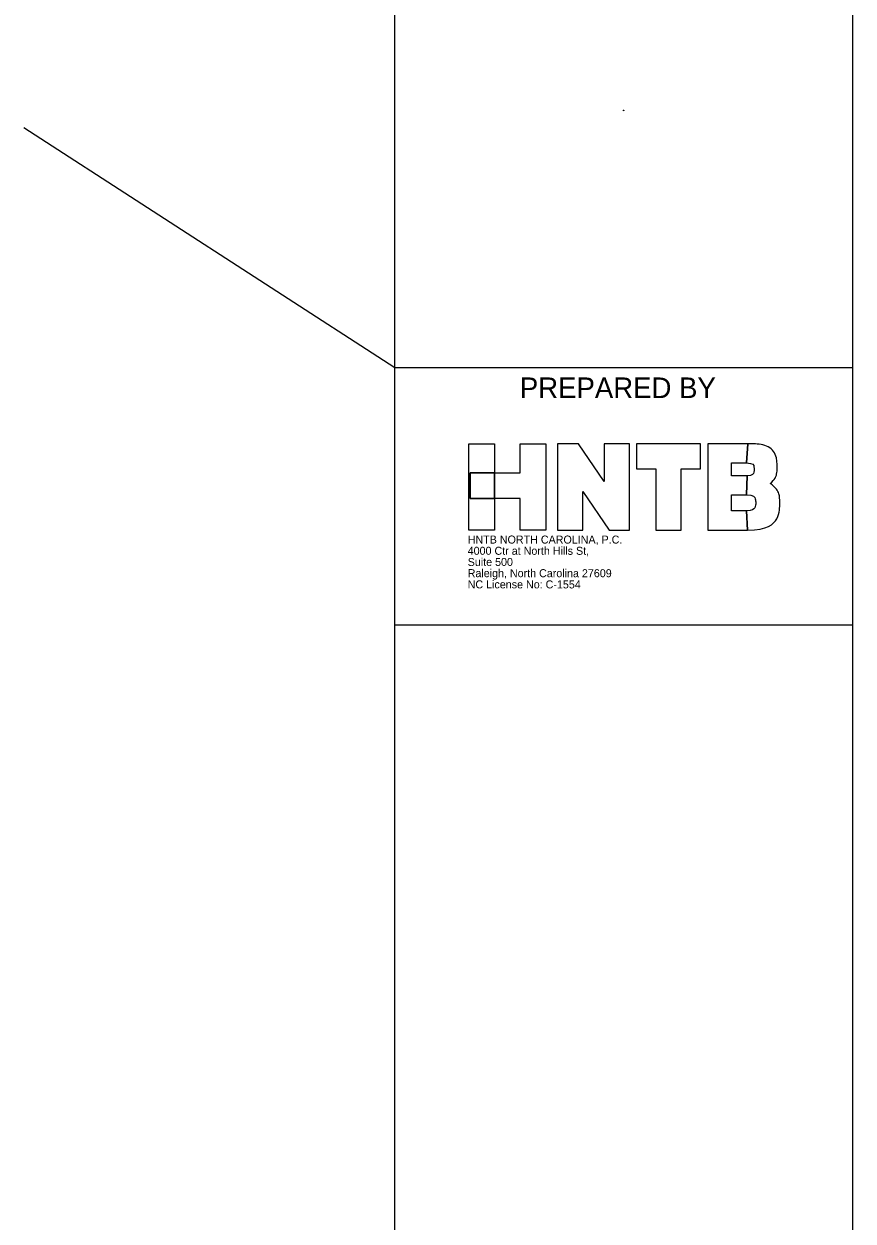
# Model space of a CAD drawing. Extents: x 2.51 to 3.27, y 0.05 to 1.8.
# Drawn here: x 2.5091 to 2.8109, y 0.9253 to 1.3613 of the extents above; entities that cross this region are included whole.
import ezdxf

# ---------------------------------------------------------------- set-up
doc = ezdxf.new("R2010")
doc.units = 0
for name, color, linetype in [('Default', 7, 'Continuous'), ('Draft_RDY_Construction_Class_Element', 7, 'Continuous'), ('Raster_Level_0', 7, 'Continuous'), ('Scratch_Level_0', 7, 'Continuous'), ('Sheet_PE_Seal_Cell', 7, 'Continuous'), ('Sheet_Plan_CELL', 7, 'Continuous')]:
    doc.layers.add(name, color=color, linetype=linetype)

msp = doc.modelspace()

# ---------------------------------------------------------------- linework, layer by layer
at = {"layer": 'Default'}
msp.add_line((2.64404, 1.23602), (2.50908, 1.3234), dxfattribs=at)
at = {"layer": 'Draft_RDY_Construction_Class_Element'}
for p, q in [((2.64413, 0.26193), (2.64413, 1.7958)), ((2.81075, 1.7958), (2.81075, 0.27071))]:
    msp.add_line(p, q, dxfattribs=at)
at = {"layer": 'Raster_Level_0'}
msp.add_lwpolyline([(2.67148, 1.19773), (2.68042, 1.19773), (2.68042, 1.18848), (2.67148, 1.18848)], close=True, dxfattribs=at)
at = {"layer": 'Scratch_Level_0'}
for p, q in [((2.67109, 1.17693), (2.67109, 1.20834)), ((2.67109, 1.20834), (2.68042, 1.20834)), ((2.68042, 1.20834), (2.68042, 1.19773)), ((2.68971, 1.19773), (2.68971, 1.20834)), ((2.68971, 1.20834), (2.69904, 1.20834)), ((2.69904, 1.20834), (2.69904, 1.17693)), ((2.711, 1.20834), (2.70332, 1.20834)), ((2.70332, 1.20834), (2.70332, 1.17693)), ((2.72031, 1.19463), (2.711, 1.20834)), ((2.72947, 1.20834), (2.72031, 1.20834)), ((2.72031, 1.20834), (2.72031, 1.19463)), ((2.72947, 1.17693), (2.72947, 1.20834)), ((2.7321, 1.20834), (2.7321, 1.19928)), ((2.75536, 1.20834), (2.7321, 1.20834)), ((2.75536, 1.19928), (2.75536, 1.20834)), ((2.77265, 1.20834), (2.75808, 1.20834)), ((2.75808, 1.20834), (2.75808, 1.17694)), ((2.77214, 1.20137), (2.77265, 1.20834)), ((2.77265, 1.20834), (2.77214, 1.20137)), ((2.7321, 1.19928), (2.73911, 1.19928)), ((2.73911, 1.19928), (2.73911, 1.17693)), ((2.74835, 1.17693), (2.74835, 1.19928)), ((2.74835, 1.19928), (2.75536, 1.19928)), ((2.7667, 1.19672), (2.7667, 1.20137)), ((2.7667, 1.20137), (2.77214, 1.20137)), ((2.68042, 1.19773), (2.67148, 1.19773)), ((2.67148, 1.19773), (2.67148, 1.18848)), ((2.68042, 1.18848), (2.68042, 1.19773)), ((2.68042, 1.19773), (2.68971, 1.19773)), ((2.77238, 1.19672), (2.7667, 1.19672)), ((2.77206, 1.18977), (2.77238, 1.19672)), ((2.77238, 1.19672), (2.77206, 1.18977)), ((2.71248, 1.17693), (2.71248, 1.19104)), ((2.71248, 1.19104), (2.72207, 1.17693)), ((2.67148, 1.18848), (2.68042, 1.18848)), ((2.68971, 1.18848), (2.68042, 1.18848)), ((2.68042, 1.18848), (2.68042, 1.17693)), ((2.68971, 1.17693), (2.68971, 1.18848)), ((2.7667, 1.18391), (2.7667, 1.18977)), ((2.7667, 1.18977), (2.77206, 1.18977)), ((2.77215, 1.18391), (2.7667, 1.18391)), ((2.77252, 1.17694), (2.77215, 1.18391)), ((2.77215, 1.18391), (2.77252, 1.17694)), ((2.68042, 1.17693), (2.67109, 1.17693)), ((2.69904, 1.17693), (2.68971, 1.17693)), ((2.70332, 1.17693), (2.71248, 1.17693)), ((2.72207, 1.17693), (2.72947, 1.17693)), ((2.73911, 1.17693), (2.74835, 1.17693)), ((2.75808, 1.17694), (2.77252, 1.17694))]:
    msp.add_line(p, q, dxfattribs=at)
for points in [[(2.78073, 1.1939), (2.78249, 1.19536), (2.78328, 1.1976), (2.78328, 1.19918), (2.78328, 1.20483), (2.77921, 1.20834), (2.77265, 1.20834), (2.77265, 1.20834), (2.77263, 1.20834), (2.7726, 1.20834)], [(2.77214, 1.20137), (2.77463, 1.20137), (2.7749, 1.19972), (2.7749, 1.19901), (2.7749, 1.19822), (2.77437, 1.19672), (2.77238, 1.19672)], [(2.77252, 1.17694), (2.77975, 1.17694), (2.78423, 1.18097), (2.78423, 1.18748), (2.78423, 1.19), (2.78292, 1.19243), (2.78073, 1.1939)], [(2.77206, 1.18977), (2.77488, 1.18977), (2.77546, 1.18819), (2.77546, 1.18688), (2.77546, 1.18502), (2.77422, 1.18391), (2.77215, 1.18391)]]:
    msp.add_open_spline(points, degree=3, dxfattribs=at)
at = {"layer": 'Sheet_Plan_CELL'}
for p, q in [((2.81071, 1.23602), (2.64404, 1.23602)), ((2.8109, 1.14226), (2.64424, 1.14226))]:
    msp.add_line(p, q, dxfattribs=at)
msp.add_circle((2.72737, 1.32977), 0.0001, dxfattribs=at)

# ---------------------------------------------------------------- texts
at = {"layer": 'Sheet_PE_Seal_Cell'}
for s, height, p in [('HNTB NORTH CAROLINA, P.C.', 0.0029148, (2.67062, 1.17203)), ('4000 Ctr at North Hills St,', 0.0029148, (2.67062, 1.16794)), ('Suite 500', 0.002915, (2.67062, 1.16386)), ('Raleigh, North Carolina 27609', 0.0029148, (2.67061, 1.15978)), ('NC License No: C-1554', 0.0029148, (2.67061, 1.1557))]:
    msp.add_text(s, height=height, rotation=359.9739, dxfattribs=at).set_placement(p)
at = {"layer": 'Sheet_Plan_CELL'}
msp.add_text('PREPARED BY', height=0.0075, rotation=0, dxfattribs=at).set_placement((2.68961, 1.225))

doc.saveas('drawing.dxf')
